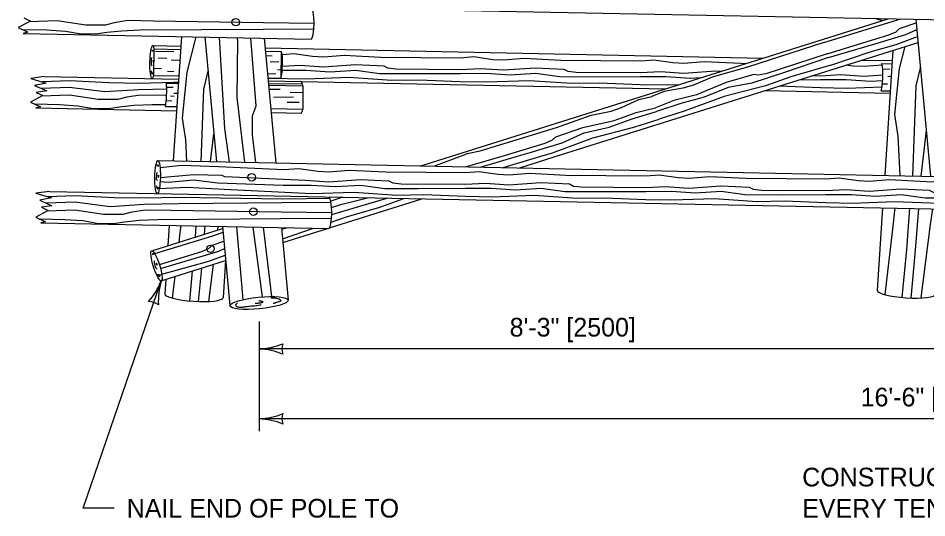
# Model space of a CAD drawing. Extents: x 49991.4 to 50021, y 49987.6 to 50011.4.
# Drawn here: x 50009.165 to 50012.08, y 49990.289 to 49991.893 of the extents above; entities that cross this region are included whole.
import ezdxf

# ---------------------------------------------------------------- set-up
doc = ezdxf.new("R2010")
doc.units = 0
for name, color, linetype in [('Level 1', 7, 'Continuous'), ('Level 2', 7, 'Continuous'), ('Level 3', 7, 'Continuous')]:
    doc.layers.add(name, color=color, linetype=linetype)

msp = doc.modelspace()

# ---------------------------------------------------------------- linework, layer by layer
at = {"layer": 'Level 1'}
for p, q in [((50009.7667, 49991.9345), (50012.238, 49991.8861)), ((50009.183, 49991.8944), (50009.204, 49991.8841)), ((50010.4569, 49991.4191), (50011.9557, 49991.8916)), ((50011.9357, 49991.8854), (50011.9131, 49991.8925)), ((50009.204, 49991.8841), (50009.1647, 49991.8632)), ((50009.1647, 49991.8632), (50009.1961, 49991.8483)), ((50012.0454, 49991.8899), (50012.0923, 49991.3859)), ((50009.1811, 49991.8445), (50010.1044, 49991.8265)), ((50009.1961, 49991.8483), (50009.1812, 49991.8445)), ((50009.6882, 49991.8346), (50009.6625, 49991.4352)), ((50009.7635, 49991.8331), (50009.8009, 49991.4324)), ((50009.5963, 49991.8052), (50009.6862, 49991.8034)), ((50009.9542, 49991.8294), (50009.9916, 49991.4285)), ((50010.8882, 49991.4487), (50012.0523, 49991.8157)), ((50009.5996, 49991.7098), (50009.6013, 49991.7948)), ((50009.6013, 49991.7948), (50009.6855, 49991.7931)), ((50009.6056, 49991.7875), (50009.664, 49991.7864)), ((50009.9572, 49991.7979), (50011.5555, 49991.7655)), ((50009.9581, 49991.7876), (50010.01, 49991.7865)), ((50010.0083, 49991.7012), (50010.01, 49991.7865)), ((50011.9707, 49991.79), (50011.9449, 49991.3889)), ((50009.6142, 49991.7664), (50009.6418, 49991.7648)), ((50009.6553, 49991.7592), (50009.6833, 49991.7588)), ((50009.9595, 49991.7732), (50009.9796, 49991.7725)), ((50009.9736, 49991.7546), (50010.0012, 49991.7535)), ((50011.8726, 49991.759), (50011.9686, 49991.7571)), ((50011.9363, 49991.7474), (50011.9679, 49991.7468)), ((50009.6, 49991.7324), (50009.6245, 49991.732)), ((50009.6434, 49991.7233), (50009.664, 49991.7222)), ((50009.9969, 49991.7279), (50010.0089, 49991.7284)), ((50011.9385, 49991.7302), (50011.9612, 49991.7293)), ((50009.2485, 49991.706), (50009.2049, 49991.7)), ((50009.2049, 49991.7), (50009.2549, 49991.6851)), ((50009.2485, 49991.706), (50009.6794, 49991.6976)), ((50009.5996, 49991.7098), (50009.68, 49991.7081)), ((50009.9649, 49991.7154), (50009.9909, 49991.7145)), ((50009.9661, 49991.7021), (50010.0083, 49991.7012)), ((50009.9671, 49991.6919), (50010.0715, 49991.6899)), ((50010.0083, 49991.7012), (50010.0083, 49991.7012)), ((50010.0716, 49991.6899), (50011.2431, 49991.667)), ((50011.9552, 49991.7067), (50011.9653, 49991.7062)), ((50009.2549, 49991.6851), (50009.2172, 49991.6776)), ((50009.2172, 49991.6776), (50009.2564, 49991.6597)), ((50009.2564, 49991.6597), (50009.2229, 49991.655)), ((50009.6402, 49991.6852), (50009.6785, 49991.6844)), ((50009.6411, 49991.6718), (50009.6617, 49991.6718)), ((50009.9683, 49991.6788), (50010.0779, 49991.6766)), ((50009.9695, 49991.6657), (50010.0055, 49991.6654)), ((50010.0779, 49991.6766), (50010.0779, 49991.6017)), ((50011.5608, 49991.6607), (50011.9619, 49991.6529)), ((50011.9342, 49991.6606), (50011.9623, 49991.66)), ((50011.9378, 49991.6826), (50011.9541, 49991.6826)), ((50009.2439, 49991.6447), (50009.2046, 49991.6238)), ((50009.2229, 49991.655), (50009.2439, 49991.6447)), ((50009.6399, 49991.6293), (50009.6574, 49991.6281)), ((50009.6531, 49991.6435), (50009.665, 49991.6425)), ((50009.6639, 49991.6528), (50009.6765, 49991.6522)), ((50009.9844, 49991.6402), (50010.0476, 49991.6407)), ((50010.0374, 49991.6561), (50010.0779, 49991.6549)), ((50009.2046, 49991.6238), (50009.236, 49991.6089)), ((50009.236, 49991.6089), (50009.2209, 49991.605)), ((50009.2209, 49991.605), (50009.6728, 49991.5963)), ((50009.6369, 49991.6103), (50009.6737, 49991.6096)), ((50009.9753, 49991.6037), (50010.0779, 49991.6017)), ((50010.0282, 49991.6238), (50010.0665, 49991.6232)), ((50009.9765, 49991.5903), (50010.0722, 49991.5885)), ((50010.4982, 49991.4183), (50010.5962, 49991.4546)), ((50009.613, 49991.4362), (50009.8311, 49991.4318)), ((50009.8311, 49991.4318), (50012.1135, 49991.3855)), ((50010.6003, 49991.4162), (50010.7247, 49991.452)), ((50010.6484, 49991.4152), (50010.7702, 49991.4511)), ((50010.7212, 49991.4137), (50010.838, 49991.4497)), ((50010.774, 49991.4127), (50010.8882, 49991.4487)), ((50009.2653, 49991.3371), (50009.2217, 49991.331)), ((50009.2653, 49991.3371), (50009.8243, 49991.3261)), ((50009.2217, 49991.331), (50009.2716, 49991.3161)), ((50009.2716, 49991.3161), (50009.2339, 49991.3086)), ((50009.2339, 49991.3086), (50009.2732, 49991.2907)), ((50009.8234, 49991.3261), (50012.2947, 49991.2777)), ((50010.1639, 49991.2203), (50010.4599, 49991.3136)), ((50010.2065, 49991.3186), (50010.1675, 49991.3063)), ((50010.1706, 49991.2632), (50010.3261, 49991.3092)), ((50010.2004, 49991.2953), (50010.286, 49991.317)), ((50009.2732, 49991.2907), (50009.2397, 49991.286)), ((50009.2397, 49991.286), (50009.2606, 49991.2758)), ((50010.1701, 49991.2859), (50010.2004, 49991.2953)), ((50010.2181, 49991.2552), (50010.3255, 49991.2865)), ((50011.9382, 49991.2847), (50011.9211, 49991.0198)), ((50009.2606, 49991.2758), (50009.2214, 49991.2548)), ((50009.2214, 49991.2548), (50009.2528, 49991.2399)), ((50009.2378, 49991.2361), (50010.1611, 49991.2181)), ((50009.2528, 49991.2399), (50009.2379, 49991.2361)), ((50009.6492, 49991.2281), (50009.645, 49991.1631)), ((50009.8202, 49991.2248), (50009.8439, 49990.9703)), ((50010.0091, 49991.221), (50010.0309, 49990.9876)), ((50010.0096, 49991.2157), (50010.0268, 49991.2207)), ((50009.5932, 49991.1468), (50009.8208, 49991.2185)), ((50010.0136, 49991.173), (50010.1571, 49991.2182)), ((50009.624, 49991.0501), (50009.8304, 49991.1151)), ((50009.8301, 49991.1151), (50009.8226, 49990.9962)), ((50009.638, 49991.0545), (50009.635, 49991.0084))]:
    msp.add_line(p, q, dxfattribs=at)
for points in [[(50011.7492, 49991.8151), (50011.9972, 49991.8908)], [(50009.9521, 49991.8787), (50009.5984, 49991.8841), (50009.5162, 49991.8854), (50009.4731, 49991.8787), (50009.4443, 49991.8714), (50009.3819, 49991.8714), (50009.2895, 49991.8853), (50009.1999, 49991.882)], [(50010.1139, 49991.8762), (50009.9521, 49991.8787)], [(50011.7605, 49991.7793), (50011.9585, 49991.8396), (50011.9821, 49991.8497), (50011.9922, 49991.8597), (50012.0465, 49991.8785)], [(50012.0335, 49991.8901), (50012.0335, 49991.8901)], [(50009.9507, 49991.8574), (50009.5545, 49991.8546), (50009.4964, 49991.852), (50009.4496, 49991.8469), (50009.4142, 49991.8417), (50009.3603, 49991.843), (50009.3164, 49991.8507), (50009.2569, 49991.8546), (50009.1793, 49991.8563)], [(50009.7058, 49991.4343), (50009.7021, 49991.5027), (50009.6919, 49991.5724), (50009.7069, 49991.72), (50009.7359, 49991.8337)], [(50010.1132, 49991.8586), (50009.9507, 49991.8574)], [(50011.7643, 49991.7671), (50011.91, 49991.8096), (50012.0131, 49991.8407), (50012.0485, 49991.8567)], [(50011.7721, 49991.7426), (50011.8982, 49991.7856), (50011.9816, 49991.8086), (50012.0506, 49991.8343)], [(50009.8431, 49991.4315), (50009.8274, 49991.5395), (50009.8105, 49991.8322)], [(50009.8922, 49991.4305), (50009.8671, 49991.6386), (50009.8692, 49991.8216), (50009.8674, 49991.8311)], [(50009.9274, 49991.4298), (50009.9169, 49991.5188), (50009.9164, 49991.5797), (50009.9283, 49991.6114), (50009.9109, 49991.8303)], [(50011.7492, 49991.8151), (50011.5052, 49991.7358), (50011.3919, 49991.704), (50011.3317, 49991.6784), (50011.2975, 49991.669), (50011.2371, 49991.6579), (50011.198, 49991.6414)], [(50010.5843, 49991.7655), (50010.3277, 49991.7675), (50010.2102, 49991.7734), (50010.1449, 49991.7681), (50010.1095, 49991.77), (50010.0487, 49991.7788), (50010.0116, 49991.776)], [(50011.7605, 49991.7793), (50011.5638, 49991.7151), (50011.5388, 49991.7099), (50011.5246, 49991.7122), (50011.4361, 49991.6871), (50011.3413, 49991.6477), (50011.2685, 49991.6288), (50011.2093, 49991.6055)], [(50011.9949, 49991.3879), (50011.9883, 49991.5141), (50011.9779, 49991.5838), (50011.993, 49991.7314), (50012.0112, 49991.8028)], [(50009.5859, 49991.7517), (50009.5859, 49991.7517)], [(50011.1622, 49991.7554), (50010.9057, 49991.7575), (50010.7881, 49991.7634), (50010.7228, 49991.7581), (50010.6874, 49991.76), (50010.6266, 49991.7688), (50010.5843, 49991.7655)], [(50011.4977, 49991.7473), (50011.4836, 49991.7474), (50011.3661, 49991.7533), (50011.3008, 49991.748), (50011.2654, 49991.7499), (50011.2046, 49991.7587), (50011.1622, 49991.7554)], [(50011.7643, 49991.7671), (50011.6208, 49991.7183), (50011.5184, 49991.6847), (50011.4428, 49991.6705), (50011.3662, 49991.6394), (50011.2908, 49991.6196), (50011.2131, 49991.5933)], [(50009.7514, 49991.4334), (50009.7602, 49991.6649), (50009.7738, 49991.723)], [(50010.5834, 49991.7151), (50010.4317, 49991.7143), (50010.324, 49991.7149), (50010.2477, 49991.7255), (50010.1654, 49991.7203), (50010.0875, 49991.7255), (50010.0118, 49991.7252)], [(50010.5836, 49991.7278), (50010.3767, 49991.7294), (50010.3512, 49991.7324), (50010.3386, 49991.7391), (50010.2467, 49991.7433), (50010.1444, 49991.7361), (50010.0693, 49991.7412), (50010.0126, 49991.7382)], [(50011.1616, 49991.7177), (50010.9546, 49991.7193), (50010.9292, 49991.7224), (50010.9165, 49991.729), (50010.8246, 49991.7333), (50010.7223, 49991.726), (50010.6472, 49991.7311), (50010.5836, 49991.7278)], [(50011.419, 49991.7224), (50011.4026, 49991.7232), (50011.3002, 49991.7159), (50011.2252, 49991.721), (50011.1616, 49991.7177)], [(50011.7721, 49991.7426), (50011.6441, 49991.7055), (50011.5626, 49991.6765), (50011.4294, 49991.6418), (50011.3017, 49991.5943), (50011.2209, 49991.5688)], [(50011.9372, 49991.7426), (50011.8787, 49991.7379), (50011.8433, 49991.7398), (50011.8216, 49991.743)], [(50012.0353, 49991.3871), (50012.0463, 49991.6763), (50012.0599, 49991.7344)], [(50009.6787, 49991.6867), (50009.6638, 49991.6866), (50009.5519, 49991.684), (50009.4555, 49991.6853), (50009.3294, 49991.6917), (50009.2431, 49991.6886)], [(50010.5829, 49991.6893), (50010.4498, 49991.6948), (50010.3633, 49991.6931), (50010.226, 49991.7025), (50010.0898, 49991.6979), (50009.9663, 49991.7001)], [(50011.1609, 49991.6792), (50011.0277, 49991.6847), (50010.9412, 49991.6831), (50010.8039, 49991.6924), (50010.6677, 49991.6878), (50010.5829, 49991.6893)], [(50011.1613, 49991.705), (50011.0097, 49991.7043), (50010.9019, 49991.7048), (50010.8257, 49991.7154), (50010.7433, 49991.7102), (50010.6654, 49991.7154), (50010.5834, 49991.7151)], [(50011.355, 49991.7023), (50011.3212, 49991.7001), (50011.2433, 49991.7053), (50011.1613, 49991.705)], [(50011.7393, 49991.6949), (50011.6682, 49991.6946)], [(50011.7395, 49991.7076), (50011.7103, 49991.7079)], [(50011.9386, 49991.6925), (50011.8991, 49991.69), (50011.8212, 49991.6953), (50011.7393, 49991.6949)], [(50011.9391, 49991.7102), (50011.8781, 49991.7058), (50011.8031, 49991.711), (50011.7395, 49991.7076)], [(50009.6413, 49991.6656), (50009.5519, 49991.6636), (50009.4426, 49991.6567), (50009.3294, 49991.6713), (50009.2383, 49991.6679)], [(50010.0766, 49991.6823), (50009.9681, 49991.6812)], [(50011.2811, 49991.679), (50011.2456, 49991.6778), (50011.1609, 49991.6792)], [(50011.7388, 49991.6692), (50011.6056, 49991.6746), (50011.6048, 49991.6746)], [(50011.9364, 49991.6715), (50011.8236, 49991.6677), (50011.7388, 49991.6692)], [(50009.6411, 49991.6447), (50009.6383, 49991.6447), (50009.5561, 49991.646), (50009.513, 49991.6393), (50009.4842, 49991.632), (50009.4218, 49991.632), (50009.3294, 49991.6459), (50009.2398, 49991.6426)], [(50010.6468, 49991.4676), (50010.892, 49991.5425), (50011.0031, 49991.5815), (50011.0672, 49991.595), (50011.1007, 49991.6068), (50011.1564, 49991.6325), (50011.198, 49991.6414)], [(50009.638, 49991.6155), (50009.5944, 49991.6152), (50009.5363, 49991.6126), (50009.4895, 49991.6075), (50009.4541, 49991.6023), (50009.4002, 49991.6036), (50009.3563, 49991.6113), (50009.2968, 49991.6152), (50009.2192, 49991.6169)], [(50010.7247, 49991.452), (50010.8561, 49991.4921), (50010.8796, 49991.5022), (50010.8898, 49991.5122), (50010.9767, 49991.5423), (50011.0769, 49991.5644), (50011.1474, 49991.5907), (50011.2093, 49991.6055)], [(50010.7702, 49991.4511), (50010.8076, 49991.4619), (50010.9106, 49991.4931), (50010.9808, 49991.5249), (50011.0613, 49991.5432), (50011.1345, 49991.5703), (50011.2131, 49991.5933)], [(50010.838, 49991.4497), (50010.8791, 49991.461), (50011.0081, 49991.509), (50011.14, 49991.5433), (50011.2209, 49991.5688)], [(50009.7823, 49991.4328), (50009.7925, 49991.5217)], [(50012.0618, 49991.3866), (50012.0787, 49991.5331)], [(50010.5962, 49991.4546), (50010.6053, 49991.4588), (50010.6468, 49991.4676)], [(50010.0176, 49991.4061), (50009.8078, 49991.4163), (50009.6902, 49991.4201), (50009.6198, 49991.4132)], [(50010.6011, 49991.3965), (50010.3445, 49991.3986), (50010.227, 49991.4044), (50010.1617, 49991.3991), (50010.1263, 49991.4011), (50010.0655, 49991.4098), (50010.0176, 49991.4061)], [(50011.179, 49991.3864), (50010.9224, 49991.3885), (50010.8049, 49991.3944), (50010.7396, 49991.3891), (50010.7042, 49991.391), (50010.6434, 49991.3998), (50010.6011, 49991.3965)], [(50010.0144, 49991.3561), (50009.805, 49991.3636), (50009.7286, 49991.3728), (50009.6463, 49991.3662), (50009.6201, 49991.3675)], [(50009.828, 49991.3836), (50009.8192, 49991.388), (50009.7272, 49991.3907), (50009.6208, 49991.3812)], [(50010.6004, 49991.3588), (50010.3935, 49991.3604), (50010.368, 49991.3635), (50010.3554, 49991.3701), (50010.2635, 49991.3744), (50010.1611, 49991.3671), (50010.0861, 49991.3722), (50009.828, 49991.3836)], [(50011.757, 49991.3763), (50011.5004, 49991.3784), (50011.3829, 49991.3843), (50011.3176, 49991.379), (50011.2822, 49991.3809), (50011.2214, 49991.3897), (50011.179, 49991.3864)], [(50012.3004, 49991.3666), (50012.0783, 49991.3683), (50011.9608, 49991.3742), (50011.8955, 49991.3689), (50011.8601, 49991.3708), (50011.7993, 49991.3796), (50011.7569, 49991.3763)], [(50009.8254, 49991.3435), (50009.7072, 49991.3495), (50009.6173, 49991.3449)], [(50010.5997, 49991.3203), (50010.4666, 49991.3258), (50010.3801, 49991.3241), (50010.2428, 49991.3335), (50010.1066, 49991.3289), (50009.8254, 49991.3435)], [(50010.6002, 49991.3461), (50010.4485, 49991.3453), (50010.3408, 49991.3459), (50010.2645, 49991.3565), (50010.1821, 49991.3513), (50010.1043, 49991.3565), (50010.0144, 49991.3561)], [(50011.1781, 49991.336), (50011.0264, 49991.3353), (50010.9187, 49991.3359), (50010.8424, 49991.3464), (50010.7601, 49991.3412), (50010.6822, 49991.3464), (50010.6002, 49991.3461)], [(50011.1784, 49991.3487), (50010.9714, 49991.3504), (50010.946, 49991.3534), (50010.9333, 49991.36), (50010.8414, 49991.3643), (50010.7391, 49991.357), (50010.664, 49991.3621), (50010.6004, 49991.3588)], [(50011.7563, 49991.3387), (50011.5494, 49991.3403), (50011.5239, 49991.3433), (50011.5113, 49991.35), (50011.4193, 49991.3542), (50011.317, 49991.3469), (50011.242, 49991.3521), (50011.1784, 49991.3487)], [(50012.298, 49991.3289), (50012.1018, 49991.3332), (50012.0892, 49991.3399), (50011.9972, 49991.3441), (50011.8949, 49991.3369), (50011.8199, 49991.342), (50011.7562, 49991.3387)], [(50010.0115, 49991.3125), (50009.6806, 49991.3176), (50009.5687, 49991.315), (50009.4723, 49991.3163), (50009.3462, 49991.3227), (50009.2599, 49991.3196)], [(50010.1654, 49991.314), (50010.0115, 49991.3125)], [(50010.3255, 49991.2865), (50010.328, 49991.2871), (50010.4019, 49991.3148)], [(50010.3261, 49991.3092), (50010.3481, 49991.3158)], [(50011.1777, 49991.3103), (50011.0445, 49991.3157), (50010.958, 49991.3141), (50010.8207, 49991.3235), (50010.6845, 49991.3188), (50010.5997, 49991.3203)], [(50011.7556, 49991.3002), (50011.6224, 49991.3056), (50011.5359, 49991.304), (50011.3986, 49991.3134), (50011.2624, 49991.3088), (50011.1777, 49991.3103)], [(50011.756, 49991.326), (50011.6044, 49991.3252), (50011.4966, 49991.3258), (50011.4204, 49991.3364), (50011.338, 49991.3311), (50011.2601, 49991.3364), (50011.1781, 49991.336)], [(50012.1089, 49991.3155), (50012.0746, 49991.3157), (50011.9983, 49991.3263), (50011.9159, 49991.3211), (50011.838, 49991.3263), (50011.756, 49991.326)], [(50010.0108, 49991.3004), (50009.6806, 49991.2972), (50009.5687, 49991.2946), (50009.4594, 49991.2877), (50009.3462, 49991.3023), (50009.2551, 49991.299)], [(50010.1683, 49991.302), (50010.0108, 49991.3004)], [(50012.2955, 49991.2917), (50011.9766, 49991.3033), (50011.8404, 49991.2987), (50011.7556, 49991.3002)], [(50011.9462, 49991.0056), (50011.971, 49991.2164), (50011.9789, 49991.2839)], [(50012.0014, 49990.9965), (50012.0155, 49991.151), (50012.0259, 49991.2829)], [(50012.0299, 49990.9948), (50012.044, 49991.1481), (50012.0546, 49991.2824)], [(50012.0622, 49990.995), (50012.092, 49991.2313), (50012.099, 49991.2815)], [(50010.0088, 49991.2703), (50009.6551, 49991.2757), (50009.5729, 49991.277), (50009.5298, 49991.2703), (50009.501, 49991.263), (50009.4386, 49991.263), (50009.3462, 49991.2769), (50009.2566, 49991.2736)], [(50010.1699, 49991.2502), (50010.0074, 49991.249)], [(50010.1706, 49991.2678), (50010.0088, 49991.2703)], [(50010.1687, 49991.2383), (50010.2181, 49991.2552)], [(50010.0074, 49991.249), (50009.6112, 49991.2462), (50009.5531, 49991.2436), (50009.5063, 49991.2385), (50009.4709, 49991.2333), (50009.417, 49991.2346), (50009.3731, 49991.2423), (50009.3136, 49991.2462), (50009.236, 49991.2479)], [(50009.6813, 49991.1746), (50009.6849, 49991.2051), (50009.6875, 49991.2274)], [(50009.7334, 49991.191), (50009.7362, 49991.2264)], [(50009.7629, 49991.2003), (50009.7649, 49991.2259)], [(50009.8051, 49991.2136), (50009.8066, 49991.225)], [(50009.8863, 49990.9899), (50009.8665, 49991.2238)], [(50009.9484, 49990.9986), (50009.919, 49991.2228)], [(50009.9784, 49990.9996), (50009.952, 49991.2221)], [(50009.6028, 49991.1375), (50009.7897, 49991.1949), (50009.8219, 49991.2062)], [(50010.0125, 49991.1848), (50010.1125, 49991.2191)], [(50009.6177, 49991.1022), (50009.7535, 49991.1445), (50009.7771, 49991.1546), (50009.7874, 49991.1645), (50009.8246, 49991.1774)], [(50009.6215, 49991.0891), (50009.8082, 49991.1455), (50009.8268, 49991.1539)], [(50009.6253, 49991.0716), (50009.7767, 49991.1134), (50009.8288, 49991.1328)], [(50009.5984, 49991.097), (50009.5984, 49991.097)], [(50009.7153, 49990.9851), (50009.7241, 49991.0816)], [(50009.7438, 49990.9834), (50009.7537, 49991.0909)], [(50009.7761, 49990.9836), (50009.7911, 49991.1028)], [(50009.6602, 49990.9942), (50009.6683, 49991.064)]]:
    msp.add_lwpolyline(points, dxfattribs=at)
for centre in [(50009.8626, 49991.8804), (50009.914, 49991.3824), (50009.9193, 49991.272), (50009.7818, 49991.1529)]:
    msp.add_circle(centre, 0.012, dxfattribs=at)
for centre, major_axis, ratio, start_param, end_param in [((50010.1044, 49991.8773), (0, -0.0508), 0.187855, 6.283183, 9.424783), ((50009.5952, 49991.7522), (0.0011, 0.053), 0.166587, 5.650345, 10.07109), ((50010.0039, 49991.7439), (0.0011, 0.053), 0.166587, 3.77745, 5.649064), ((50011.9302, 49991.7048), (0.0011, 0.053), 0.166587, 3.729315, 5.649064), ((50010.0715, 49991.6391), (0, -0.0508), 0.187855, 2.40162, 3.141598), ((50009.6325, 49991.653), (0.0011, 0.053), 0.166587, 3.77745, 5.368261), ((50010.0715, 49991.6391), (0, -0.0508), 0.187855, 6.283183, 7.024542), ((50010.1611, 49991.2689), (0, -0.0508), 0.187855, 6.283183, 9.424783), ((50012.0148, 49991.0138), (-0.0937, 0.0061), 0.194104, 0.000064, 3.132664), ((50009.7287, 49991.0024), (-0.0937, 0.0061), 0.194104, 0.000064, 3.132664)]:
    msp.add_ellipse(centre, major_axis=major_axis, ratio=ratio, start_param=start_param, end_param=end_param, dxfattribs=at)
for centre, major_axis, ratio in [((50009.612, 49991.3832), (0.0011, 0.053), 0.166587), ((50009.6085, 49991.0984), (-0.0153, 0.0484), 0.196346), ((50009.9376, 49990.9788), (0.0932, 0.0089), 0.201992)]:
    msp.add_ellipse(centre, major_axis=major_axis, ratio=ratio, dxfattribs=at)
for points in [[(50009.5986, 49991.7866), (50009.5982, 49991.7888), (50009.5959, 49991.7903), (50009.5951, 49991.79), (50009.5935, 49991.7874)], [(50009.5935, 49991.7668), (50009.5919, 49991.7623), (50009.5916, 49991.7552), (50009.5923, 49991.7429), (50009.5947, 49991.7407)], [(50009.5974, 49991.7579), (50009.5978, 49991.7519), (50009.5994, 49991.7526), (50009.5994, 49991.7549), (50009.6002, 49991.7586)], [(50009.5915, 49991.7244), (50009.5923, 49991.7184), (50009.5938, 49991.7154), (50009.5958, 49991.7143), (50009.5962, 49991.7151), (50009.5994, 49991.721)], [(50009.6103, 49991.3978), (50009.6087, 49991.3934), (50009.6083, 49991.3862), (50009.6091, 49991.3739), (50009.6115, 49991.3717)], [(50009.6154, 49991.4176), (50009.615, 49991.4199), (50009.6127, 49991.4213), (50009.6119, 49991.421), (50009.6103, 49991.4184)], [(50009.6142, 49991.3889), (50009.6146, 49991.3829), (50009.6162, 49991.3836), (50009.6162, 49991.3859), (50009.617, 49991.3896)], [(50009.6083, 49991.3554), (50009.6091, 49991.3494), (50009.6106, 49991.3464), (50009.6126, 49991.3453), (50009.613, 49991.3461), (50009.6161, 49991.3521)], [(50009.6001, 49991.1341), (50009.5991, 49991.1362), (50009.5964, 49991.1368), (50009.5957, 49991.1362), (50009.595, 49991.1333)], [(50009.6011, 49991.1137), (50009.601, 49991.1089), (50009.6028, 49991.102), (50009.6073, 49991.0905), (50009.6102, 49991.0891)], [(50009.6076, 49991.1063), (50009.6098, 49991.1008), (50009.6111, 49991.1019), (50009.6104, 49991.104), (50009.61, 49991.1079)], [(50009.612, 49991.0727), (50009.6145, 49991.0672), (50009.6169, 49991.0648), (50009.6191, 49991.0644), (50009.6193, 49991.0652), (50009.6205, 49991.0718)], [(50009.9762, 49990.9957), (50009.9809, 49990.9957), (50009.9854, 49990.9957), (50009.9886, 49990.995), (50009.9916, 49990.9942), (50009.9963, 49990.9936), (50009.9987, 49990.9927), (50010.0024, 49990.9915), (50010.0038, 49990.9907), (50010.005, 49990.9895), (50010.0065, 49990.9881), (50010.0074, 49990.9859), (50010.0068, 49990.9848), (50010.0042, 49990.9833), (50009.9987, 49990.9816), (50009.9968, 49990.981), (50009.9901, 49990.979), (50009.9877, 49990.9785), (50009.9846, 49990.9774), (50009.9832, 49990.9774)], [(50009.868, 49990.9774), (50009.8657, 49990.9764), (50009.8631, 49990.9743), (50009.8623, 49990.9721), (50009.8636, 49990.97), (50009.8649, 49990.9679), (50009.8673, 49990.9669), (50009.8706, 49990.966), (50009.8764, 49990.9658), (50009.8847, 49990.9658), (50009.8895, 49990.9666), (50009.895, 49990.9671), (50009.9043, 49990.9686), (50009.9127, 49990.9692), (50009.9194, 49990.9697), (50009.9267, 49990.9703), (50009.9357, 49990.9718), (50009.9439, 49990.9731)], [(50009.9368, 49990.9851), (50009.94, 49990.9855), (50009.9442, 49990.9851), (50009.9464, 49990.9848), (50009.9491, 49990.9833), (50009.9493, 49990.9816), (50009.9467, 49990.9798), (50009.9424, 49990.9787), (50009.9376, 49990.978), (50009.934, 49990.9776), (50009.9285, 49990.9774), (50009.9258, 49990.9774), (50009.9249, 49990.9774)]]:
    msp.add_spline(points, degree=3, dxfattribs=at)
at = {"layer": 'Level 3'}
for p, q in [((50009.9376, 49990.9198), (50009.9376, 49990.5668)), ((50012.2237, 49990.8311), (50009.9376, 49990.8311)), ((50014.532, 49990.6068), (50009.9376, 49990.6068))]:
    msp.add_line(p, q, dxfattribs=at)
msp.add_lwpolyline([(50009.473, 49990.3198), (50009.373, 49990.3198), (50009.6234, 49991.0499)], dxfattribs=at)
for centre, radius, start, end in [((50009.4163, 49991.1306), 0.2223, 318.5208, 338.7043), ((50009.8473, 49990.9852), 0.233, 163.8921, 183.142), ((50009.5818, 49990.9286), 0.0548, 53.2036, 88.926), ((50009.9261, 49991.0639), 0.233, 272.8273, 292.0772), ((50010.0658, 49990.8311), 0.0548, 162.1388, 197.8612), ((50009.9284, 49990.609), 0.2223, 67.456, 87.6395), ((50009.9261, 49990.8395), 0.233, 272.8273, 292.0772), ((50010.0658, 49990.6068), 0.0548, 162.1388, 197.8612), ((50009.9284, 49990.3847), 0.2223, 67.456, 87.6395)]:
    msp.add_arc(centre, radius, start, end, dxfattribs=at)

# ---------------------------------------------------------------- texts
at = {"layer": 'Level 2'}
for s, p in [('8\'-3" [2500]', (50010.7416, 49990.8711)), ('16\'-6" [5000]', (50011.8677, 49990.6468))]:
    msp.add_text(s, height=0.06, rotation=0, dxfattribs=at).set_placement(p)
for s, p in [('CONSTRUCT BRACE', (50011.6802, 49990.3898)), ('NAIL END OF POLE TO', (50009.513, 49990.2898)), ('EVERY TEN POLE LENGTHS ', (50011.6802, 49990.2898))]:
    msp.add_text(s, height=0.06, dxfattribs=at).set_placement(p)

doc.saveas('drawing.dxf')
